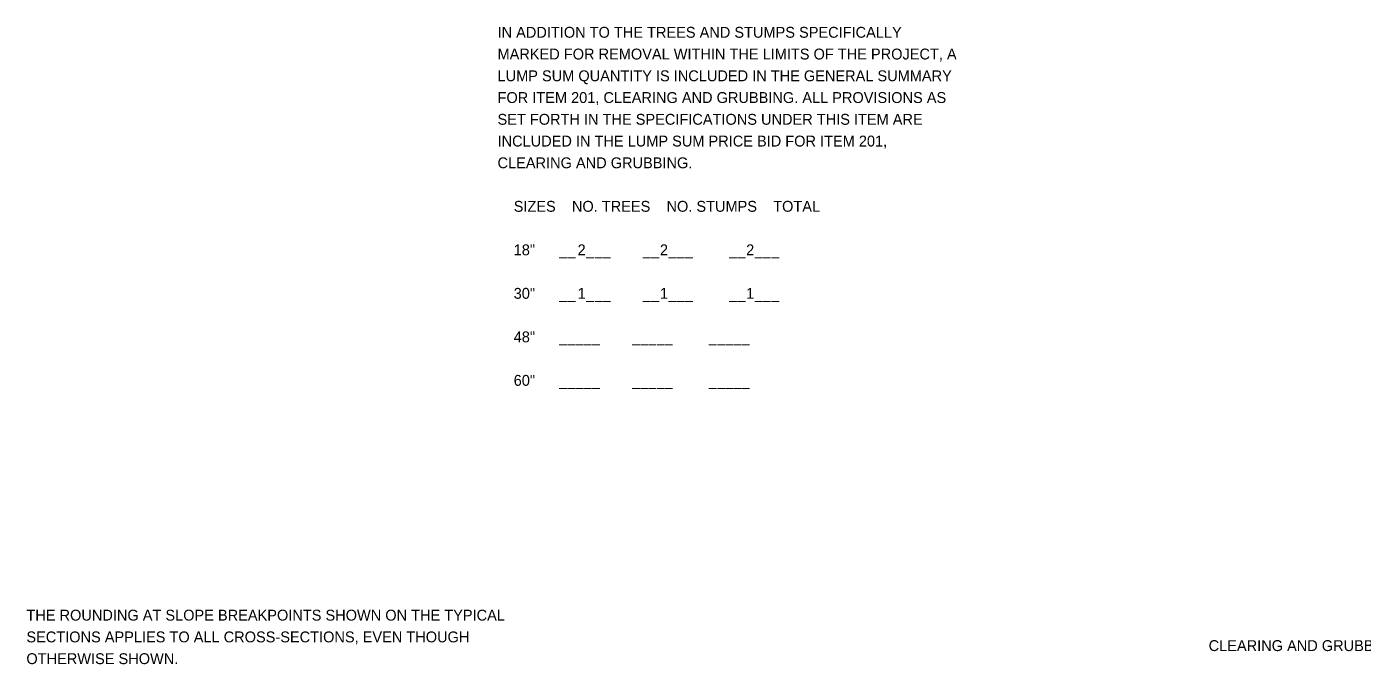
# Model space of a CAD drawing. Extents: x -286 to 93, y -30 to 99.
# Drawn here: x 0.05 to 17.24, y 25.58 to 33.78 of the extents above; entities that cross this region are included whole.
import ezdxf

# ---------------------------------------------------------------- set-up
doc = ezdxf.new("R2010")
doc.units = 0
doc.layers.add('Default', color=7, linetype='Continuous')
doc.layers.add('SH_Text', color=7, linetype='Continuous')

msp = doc.modelspace()

# ---------------------------------------------------------------- texts
at = {"layer": 'Default'}
for s, p in [('IN ADDITION TO THE TREES AND STUMPS SPECIFICALLY', (6.112, 33.642)), ('MARKED FOR REMOVAL WITHIN THE LIMITS OF THE PROJECT, A', (6.112, 33.362)), ('LUMP SUM QUANTITY IS INCLUDED IN THE GENERAL SUMMARY', (6.112, 33.082)), ('FOR ITEM 201, CLEARING AND GRUBBING. ALL PROVISIONS AS', (6.112, 32.802)), ('SET FORTH IN THE SPECIFICATIONS UNDER THIS ITEM ARE', (6.112, 32.522)), ('INCLUDED IN THE LUMP SUM PRICE BID FOR ITEM 201, ', (6.112, 32.242)), ('CLEARING AND GRUBBING.', (6.112, 31.962))]:
    msp.add_text(s, height=0.14, dxfattribs=at).set_placement(p)
at = {"layer": 'SH_Text'}
for s, p in [('    SIZES    NO. TREES    NO. STUMPS    TOTAL', (6.112, 31.402)), ('    18"      __', (6.112, 30.842)), ('2', (7.142, 30.842)), ('2', (8.202, 30.842)), ('2', (9.311, 30.842)), ('___        __', (7.254, 30.842)), ('___         __', (8.313, 30.842)), ('___', (9.423, 30.842)), ('    30"      __', (6.112, 30.282)), ('1', (7.142, 30.282)), ('1', (8.202, 30.282)), ('1', (9.311, 30.282)), ('___        __', (7.254, 30.282)), ('___         __', (8.313, 30.282)), ('___', (9.423, 30.282)), ('    48"      _____        _____         _____', (6.112, 29.722)), ('    60"      _____        _____         _____', (6.112, 29.162)), ('THE ROUNDING AT SLOPE BREAKPOINTS SHOWN ON THE TYPICAL', (0.049, 26.14)), ('SECTIONS APPLIES TO ALL CROSS-SECTIONS, EVEN THOUGH', (0.049, 25.86)), ('CLEARING AND GRUBBING', (15.263, 25.748)), ('OTHERWISE SHOWN.', (0.049, 25.58))]:
    msp.add_text(s, height=0.14, dxfattribs=at).set_placement(p)

doc.saveas('drawing.dxf')
